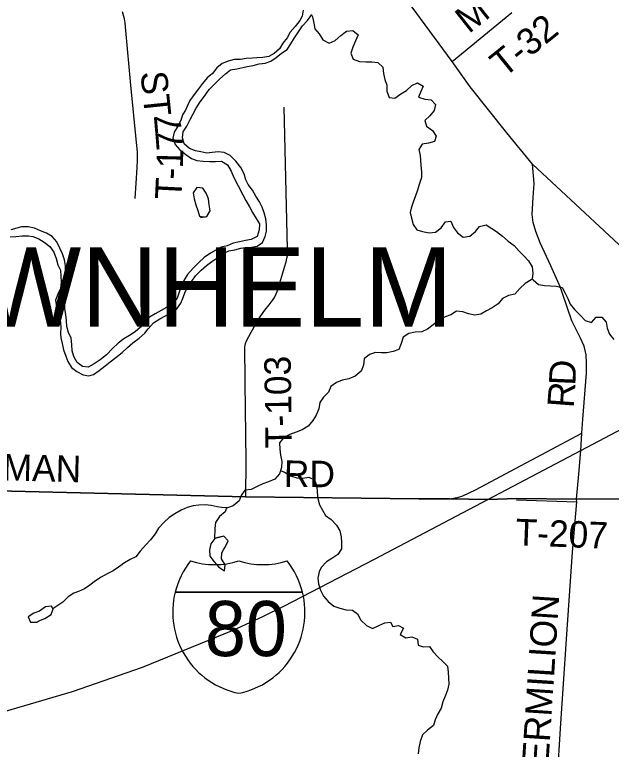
# Model space of a CAD drawing. Extents: x 1857828 to 2277390, y 930619 to 1324581.
# Drawn here: x 2017313 to 2024079, y 1218721 to 1227047 of the extents above; entities that cross this region are included whole.
import ezdxf

# ---------------------------------------------------------------- set-up
doc = ezdxf.new("R2010")
doc.units = 0
for name, color, linetype in [('GM_X_County_Road', 7, 'Continuous'), ('GM_X_County_Road_Text', 7, 'Continuous'), ('GM_X_Interstate_Location', 7, 'Continuous'), ('GM_X_Interstate_Route', 7, 'Continuous'), ('GM_X_Interstate_Shield', 7, 'Continuous'), ('GM_X_Major_River', 7, 'Continuous'), ('GM_X_Minor_Lake', 7, 'Continuous'), ('GM_X_Minor_River', 7, 'Continuous'), ('GM_X_Township', 7, 'Continuous'), ('GM_X_Township_Road', 7, 'Continuous'), ('GM_X_Township_Road_Text', 7, 'Continuous'), ('GM_X_Township_Text', 7, 'Continuous')]:
    doc.layers.add(name, color=color, linetype=linetype)

msp = doc.modelspace()

# ---------------------------------------------------------------- linework, layer by layer
at = {"layer": 'GM_X_County_Road'}
for points in [[(2023524, 1223889.1), (2023501.2, 1223954.9), (2023392.7, 1224201.3), (2023273.2, 1224460.6), (2023223.6, 1224589.3), (2023194.1, 1224690.4), (2023183.1, 1224782.4), (2023192.3, 1224973.6), (2023205.2, 1225135.4), (2023185.7, 1225354.8), (2022892.6, 1225709.1), (2022478.9, 1226229.4), (2022273.7, 1226516.8), (2021768.4, 1227206.3)], [(2023758.2, 1222462), (2023799.1, 1222984.1), (2023799.1, 1223101.8), (2023793.6, 1223193.7), (2023769.7, 1223291.2), (2023729.2, 1223379.4), (2023631.7, 1223578), (2023524, 1223889.1)], [(2023709.6, 1221840.2), (2023734.8, 1222108.8), (2023745.8, 1222303.8), (2023758.2, 1222462)], [(2022306.8, 1221569.9), (2022322.5, 1221573), (2022394.4, 1221594), (2022537.5, 1221662.4), (2023745.8, 1222303.8)], [(2023440.5, 1217534.1), (2023436.9, 1217765.8), (2023455.2, 1218056.3), (2023470, 1218403.9), (2023503, 1218957.3), (2023572.9, 1219968.6), (2023641, 1220954.2), (2023686.9, 1221526), (2023682.9, 1221555.4), (2023709.6, 1221840.2)], [(2015030.8, 1221599.6), (2015061.7, 1221639.5), (2015109.2, 1221673.3), (2015190.9, 1221697.6), (2015867.4, 1221681.1), (2019935.7, 1221581.7), (2021894.8, 1221560.6), (2022115.5, 1221560.6), (2022248.1, 1221558.4), (2022306.8, 1221569.9)]]:
    msp.add_lwpolyline(points, dxfattribs=at)
at = {"layer": 'GM_X_Interstate_Route'}
msp.add_lwpolyline([(2011181, 1217986.5), (2011653.1, 1218164.7), (2012525.4, 1218383.3), (2013202, 1218499.1), (2014599.8, 1218663.4), (2015089, 1218725), (2015558.7, 1218795.2), (2015871.8, 1218846.8), (2016489.7, 1218975.6), (2017209.2, 1219152), (2017969.7, 1219375.9), (2018763.4, 1219652.2), (2019792.4, 1220072.2), (2020127.3, 1220226), (2020366, 1220343.2), (2021393.6, 1220875.2), (2022677.5, 1221551.7), (2023734.8, 1222108.8), (2024759, 1222649.6)], dxfattribs=at)
at = {"layer": 'GM_X_Interstate_Shield'}
for p, q in [((2019134.2, 1220504.2), (2020577, 1220504.2)), ((2020577, 1220504.2), (2019134.2, 1220504.2)), ((2020577, 1220504.2), (2019134.2, 1220504.2))]:
    msp.add_line(p, q, dxfattribs=at)
for centre, start, end in [((2020043.1, 1220274.3), 141.66896, 165.80665), ((2019581.7, 1221752.3), 253.00908, 286.99093), ((2020129.6, 1221752.3), 253.00908, 286.99093), ((2019668.1, 1220274.3), 14.19335, 38.33104), ((2020043.1, 1220274.3), 165.80665, 258.46304), ((2019668.1, 1220274.3), 281.53696, 14.19335)]:
    msp.add_arc(centre, 937.5, start, end, dxfattribs=at)
at = {"layer": 'GM_X_Major_River'}
for points in [[(2020586.2, 1227097.1), (2020572.9, 1227030.8), (2020545.4, 1226980.3), (2020495.9, 1226913.5), (2020438.4, 1226848.6), (2020405, 1226784), (2020353.5, 1226723.3), (2020316, 1226658.6), (2020256.4, 1226605.8), (2020194.5, 1226572.9), (2020126.3, 1226562.1), (2020060.1, 1226557.3), (2020009.9, 1226554.8), (2019937.6, 1226551.9), (2019873.5, 1226541.1), (2019801.2, 1226540.3), (2019735.1, 1226521.5), (2019667.2, 1226492.6), (2019605.4, 1226443.8), (2019558, 1226381), (2019496.3, 1226330.1), (2019444.7, 1226269.3), (2019397.2, 1226208.6), (2019349.8, 1226141.8), (2019298.3, 1226075), (2019276.8, 1226024.6), (2019249.3, 1225964.1), (2019217.8, 1225913.6), (2019198.5, 1225847.1), (2019165, 1225782.6), (2019121.6, 1225717.8), (2019108.3, 1225647.5)], [(2019216.7, 1225652.7), (2019224, 1225721), (2019265.4, 1225783.7), (2019300.9, 1225850.3), (2019332.2, 1225916.9), (2019371.6, 1225989.6), (2019415, 1226058.3), (2019466.5, 1226125.1), (2019519.9, 1226198), (2019575.4, 1226256.8), (2019641, 1226321.8), (2019704.6, 1226376.7), (2019760.3, 1226421.5), (2019832.5, 1226434.3), (2019900.6, 1226449.2), (2019950.7, 1226461.8), (2020016.9, 1226472.6), (2020085, 1226489.4), (2020153.2, 1226496.2), (2020217.2, 1226521), (2020278.9, 1226563.9), (2020338.6, 1226612.7), (2020402.4, 1226653.6), (2020445.9, 1226718.3), (2020487.3, 1226787), (2020530.7, 1226853.7), (2020578.2, 1226920.5), (2020635.7, 1226983.3), (2020683.2, 1227050.1)], [(2017261.1, 1224528.6), (2017327.4, 1224533.4), (2017399.6, 1224542.2), (2017469.9, 1224541), (2017520.2, 1224531.6), (2017586.7, 1224508.3), (2017649.4, 1224470.9), (2017712.3, 1224419.4), (2017757.2, 1224355.8), (2017782.1, 1224285.8), (2017803, 1224213.8), (2017833.8, 1224150), (2017836.6, 1224083.8), (2017839.4, 1224015.6), (2017832.1, 1223945.3), (2017802.7, 1223880.7), (2017775.4, 1223812.2), (2017782, 1223762.1), (2017800.8, 1223698.1), (2017821.7, 1223626.1), (2017834.5, 1223554.1), (2017835.1, 1223503.9), (2017833.9, 1223435.7), (2017836.5, 1223383.5), (2017851.3, 1223319.5), (2017868.1, 1223249.4), (2017893, 1223177.5), (2017917.8, 1223115.6), (2017956.8, 1223047.8), (2018017.5, 1223004.4), (2018088.2, 1222967.1), (2018154.6, 1222955.8), (2018206.7, 1222968.4), (2018270.5, 1223013.3), (2018338.1, 1223068.3), (2018397.9, 1223113.1), (2018459.6, 1223162), (2018531.3, 1223217), (2018590.9, 1223273.8), (2018654.5, 1223328.8), (2018724.2, 1223381.7), (2018789.9, 1223436.6), (2018825.5, 1223487.2), (2018889, 1223556.2), (2018958.8, 1223599.1), (2019022.7, 1223634), (2019084.5, 1223668.8), (2019152.3, 1223713.7), (2019195.8, 1223776.4), (2019223.2, 1223840.9), (2019246.5, 1223907.4), (2019276, 1223961.9), (2019321.5, 1224026.7), (2019363, 1224089.4), (2019426.5, 1224150.3), (2019490.2, 1224205.2), (2019549.9, 1224250), (2019615.7, 1224296.9), (2019679.5, 1224341.8), (2019741.4, 1224370.6), (2019809.5, 1224383.4), (2019877.6, 1224402.3), (2019927.8, 1224406.9), (2019998, 1224413.7), (2020064.2, 1224422.5), (2020121.9, 1224465.3), (2020155.3, 1224533.9), (2020168.7, 1224594.2), (2020169.9, 1224664.5), (2020161.1, 1224734.6), (2020144.2, 1224802.6), (2020119.4, 1224866.6), (2020088.6, 1224926.4), (2020049.7, 1224990.2), (2020008.8, 1225057.9), (2019959.8, 1225123.6), (2019933.1, 1225177.4), (2019914.3, 1225245.4), (2019877.3, 1225315.2), (2019822.3, 1225386.8), (2019755.3, 1225452.3), (2019688.6, 1225485.6), (2019622.2, 1225492.9), (2019552, 1225484), (2019491.8, 1225479.3), (2019423.4, 1225492.6), (2019363, 1225505.9), (2019294.4, 1225529.2), (2019235.6, 1225584.7), (2019216.7, 1225652.7)], [(2019108.3, 1225647.5), (2019133.2, 1225575.5), (2019186.2, 1225513.9), (2019253, 1225462.5), (2019317.8, 1225417.1), (2019380.3, 1225393.8), (2019452.7, 1225386.6), (2019521, 1225383.4), (2019591.3, 1225384.2), (2019659.6, 1225387), (2019726.3, 1225345.6), (2019767.3, 1225273.8), (2019796.2, 1225210), (2019900.9, 1225006.5), (2019933.8, 1224940.7), (2019974.7, 1224870.9), (2020011.6, 1224805.1), (2020050.6, 1224737.4), (2020089.4, 1224675.6), (2020086.2, 1224607.3), (2020064.9, 1224534.9), (2019995, 1224499.9), (2019930.9, 1224489.2), (2019862.8, 1224472.3), (2019790.6, 1224457.5), (2019722.7, 1224428.6), (2019656.5, 1224413.8), (2019594.7, 1224378.9), (2019532.8, 1224346.1), (2019463, 1224297.2), (2019403.5, 1224238.3), (2019337.9, 1224175.3), (2019274.4, 1224102.4), (2019231, 1224035.7), (2019201.7, 1223967.1), (2019178.3, 1223902.6), (2019155, 1223834.1), (2019105.4, 1223773.4), (2019033.6, 1223728.4), (2018973.8, 1223693.6), (2018907.9, 1223656.7), (2018842.1, 1223617.8), (2018778.4, 1223566.9), (2018740.9, 1223506.3), (2018681.3, 1223451.4), (2018615.4, 1223412.6), (2018551.6, 1223373.7), (2018485.9, 1223322.8), (2018422.3, 1223263.9), (2018352.8, 1223192.8), (2018283.2, 1223135.8), (2018215.4, 1223090.9), (2018147.5, 1223054), (2018083.1, 1223061.3), (2018020.4, 1223104.7), (2017983.5, 1223172.5), (2017966.7, 1223236.5), (2017961.8, 1223308.7), (2017953, 1223380.8), (2017922.1, 1223446.7), (2017905.3, 1223514.7), (2017900.5, 1223582.9), (2017893.7, 1223647), (2017882.9, 1223717.1), (2017882.1, 1223785.3), (2017885.4, 1223849.6), (2017888.7, 1223917.8), (2017893.9, 1223984.1), (2017891.1, 1224056.3), (2017889.5, 1224200.8), (2017878.7, 1224268.9), (2017853.8, 1224338.8), (2017826.9, 1224402.7), (2017790, 1224472.5), (2017737.1, 1224534.1), (2017672.4, 1224571.5), (2017605.8, 1224596.8), (2017537.2, 1224626.1), (2017464.7, 1224641.3), (2017392.4, 1224642.5), (2017336.3, 1224627.8), (2017270.3, 1224609)]]:
    msp.add_lwpolyline(points, dxfattribs=at)
at = {"layer": 'GM_X_Minor_Lake'}
for points in [[(2019447.1, 1225082.9), (2019380.9, 1225087.7), (2019336, 1225028), (2019349.3, 1224959.6), (2019368.5, 1224891.2), (2019391.9, 1224826.7), (2019409.2, 1224762.3), (2019457.3, 1224755.7)], [(2019447.1, 1225082.9), (2019380.9, 1225087.7), (2019336, 1225028), (2019349.3, 1224959.6), (2019368.5, 1224891.2), (2019391.9, 1224826.7), (2019409.2, 1224762.3), (2019473.3, 1224753.5)], [(2019421.1, 1224750.1), (2019493.5, 1224761.3), (2019528.4, 1224823.1), (2019519.2, 1224891.4), (2019510, 1224961.8), (2019484.6, 1225026.3), (2019447.1, 1225082.9)], [(2019457.3, 1224755.7), (2019493.5, 1224761.3), (2019528.4, 1224823.1), (2019519.2, 1224891.4), (2019510, 1224961.8), (2019484.6, 1225026.3), (2019447.1, 1225082.9)], [(2019615.5, 1221120.9), (2019581.5, 1221110.2), (2019538, 1221049.5), (2019522.7, 1220981.1), (2019525.5, 1220910.9), (2019576.4, 1220845.3), (2019627.3, 1220785.7), (2019694.1, 1220744.3), (2019699.3, 1220810.6), (2019660.4, 1220880.4), (2019661.6, 1220948.6), (2019686.1, 1220991)], [(2019612.5, 1221120), (2019581.5, 1221110.2), (2019538, 1221049.5), (2019522.7, 1220981.1), (2019525.5, 1220910.9), (2019576.4, 1220845.3), (2019627.3, 1220785.7), (2019694.1, 1220744.3), (2019699.3, 1220810.6), (2019660.4, 1220880.4), (2019661.6, 1220948.6), (2019686.1, 1220991)], [(2019686.1, 1220991), (2019699.1, 1221013.3), (2019734.4, 1221085.9), (2019683.6, 1221135.5), (2019612.5, 1221120)], [(2019686.1, 1220991), (2019699.1, 1221013.3), (2019734.4, 1221085.9), (2019683.6, 1221135.5), (2019615.5, 1221120.7)], [(2017748.5, 1220312.8), (2017732.3, 1220344.5), (2017664.1, 1220337.7), (2017596.4, 1220286.7), (2017532.3, 1220265.9), (2017466.5, 1220223.1), (2017491.3, 1220161.1), (2017563.6, 1220164)], [(2017748.6, 1220312.8), (2017732.3, 1220344.5), (2017664.1, 1220337.7), (2017596.4, 1220286.7), (2017532.3, 1220265.9), (2017466.5, 1220223.1), (2017491.3, 1220161.1), (2017563.6, 1220164)], [(2017563.6, 1220164), (2017587.6, 1220176.3), (2017655.5, 1220205.2), (2017725.4, 1220248.1), (2017748.5, 1220312.8)], [(2017563.6, 1220164), (2017587.6, 1220176.3), (2017655.5, 1220205.2), (2017725.4, 1220248.1), (2017748.5, 1220312.8)]]:
    msp.add_lwpolyline(points, dxfattribs=at)
at = {"layer": 'GM_X_Minor_River'}
for points in [[(2020679.9, 1227045.5), (2020689.5, 1227024.1), (2020704.4, 1226952), (2020717.2, 1226886), (2020766, 1226832.3), (2020806.9, 1226762.6), (2020879.7, 1226723.3), (2020947.6, 1226756.2), (2021013.3, 1226811.1), (2021076.9, 1226862), (2021149.2, 1226868.9), (2021208, 1226819.4), (2021178.6, 1226750.8), (2021147.3, 1226678.2), (2021126, 1226611.8), (2021152.9, 1226543.9), (2021225.5, 1226516.6), (2021297.8, 1226513.4), (2021364.1, 1226514.2), (2021432.5, 1226504.9), (2021487.3, 1226451.4), (2021494.2, 1226379.2), (2021511, 1226311.2), (2021533.8, 1226249.3), (2021534.6, 1226181.1), (2021559.5, 1226109.1), (2021625.8, 1226101.8), (2021691.6, 1226150.8), (2021755.4, 1226189.6), (2021817, 1226244.5), (2021883, 1226275.4), (2021945.7, 1226236), (2021918.2, 1226177.4), (2021892.9, 1226110.9), (2021965.4, 1226091.7), (2022037.8, 1226082.5), (2022086.6, 1226028.9), (2022069.3, 1225962.5), (2022019.8, 1225899.7), (2021964.1, 1225848.9), (2021984.9, 1225782.9), (2022051.8, 1225733.6), (2022092.6, 1225671.8), (2022075.3, 1225609.4), (2022007.2, 1225590.6), (2021935, 1225581.7), (2021895.5, 1225521.1), (2021910.4, 1225453), (2021916.9, 1225402.9), (2021917.7, 1225338.7), (2021926.5, 1225266.6), (2021925.3, 1225200.4), (2021900, 1225123.8), (2021880.7, 1225059.4), (2021857.3, 1224992.9), (2021832, 1224922.4), (2021808.6, 1224855.9), (2021799.2, 1224805.6), (2021814, 1224741.6), (2021832.8, 1224669.6), (2021873.7, 1224607.9), (2021938.2, 1224588.6), (2022012.7, 1224573.3), (2022084.9, 1224584.2), (2022148.6, 1224631.1), (2022198.1, 1224697.9), (2022260.2, 1224708.6), (2022289.1, 1224636.7), (2022334, 1224575.1), (2022400.8, 1224527.7), (2022473, 1224538.5), (2022538.7, 1224591.4), (2022586.3, 1224646.2), (2022658.4, 1224667.1), (2022725.1, 1224625.7), (2022775.7, 1224590.2), (2022844.6, 1224536.8), (2022909.5, 1224481.3), (2022976.4, 1224429.9), (2023035.3, 1224368.4), (2023088.2, 1224312.9), (2023139, 1224257.3), (2023180, 1224189.5), (2023188.8, 1224119.4), (2023183.5, 1224053.1)], [(2023183.5, 1224053.1), (2023169.6, 1224040.9), (2023103.8, 1224000), (2023040.1, 1223945.1), (2022984.6, 1223880.3), (2022912.5, 1223865.4), (2022846.6, 1223830.5), (2022795.1, 1223769.7), (2022729.3, 1223726.8), (2022665.4, 1223690), (2022599.5, 1223653.1), (2022531.4, 1223640.3), (2022460.9, 1223657.5), (2022396.4, 1223678.9), (2022324, 1223686.1), (2022258.2, 1223647.2), (2022194.2, 1223622.4), (2022126.3, 1223585.5), (2022060.7, 1223530.5), (2021994.9, 1223483.6), (2021928.9, 1223454.8), (2021856.7, 1223447.9), (2021784.6, 1223435.1), (2021718.8, 1223392.2), (2021697.5, 1223321.7), (2021668.1, 1223253.1), (2021606.1, 1223230.3), (2021534, 1223215.5), (2021471.7, 1223214.8), (2021403.4, 1223220), (2021337.3, 1223197.1), (2021277.7, 1223148.3), (2021268.4, 1223076), (2021241.1, 1223007.4), (2021173.4, 1222950.5), (2021101.5, 1222921.6), (2021027.3, 1222904.6), (2020961.4, 1222877.8), (2020899.6, 1222832.9), (2020872.2, 1222768.4), (2020816.6, 1222711.6), (2020775.1, 1222652.9), (2020761.9, 1222580.6), (2020732.5, 1222510), (2020695.1, 1222447.3), (2020641.6, 1222382.5), (2020573.8, 1222341.6), (2020503.8, 1222314.7), (2020431.8, 1222289.8), (2020363.8, 1222256.9), (2020316.3, 1222194.2), (2020319.2, 1222122), (2020326, 1222055.8), (2020342.8, 1221983.8), (2020337.6, 1221913.5), (2020316.3, 1221845.1), (2020262.7, 1221784.2), (2020192.8, 1221753.3), (2020128.8, 1221728.5), (2020062.9, 1221699.7), (2019997, 1221664.8), (2019924.7, 1221657.9), (2019883.2, 1221599.3), (2019857.8, 1221536.8), (2019792.2, 1221481.8), (2019728.2, 1221459), (2019659.8, 1221462.3), (2019609.6, 1221467.7), (2019541.1, 1221483), (2019474.7, 1221492.2), (2019402.5, 1221487.4), (2019336.3, 1221480.6), (2019270.2, 1221463.8), (2019200.2, 1221432.9), (2019128.4, 1221389.9), (2019064.6, 1221349.1), (2019005, 1221290.2), (2018945.5, 1221227.3), (2018906, 1221162.6), (2018854.6, 1221093.8), (2018797, 1221035), (2018737.5, 1220968.1), (2018686, 1220903.3), (2018622.1, 1220872.4), (2018560.3, 1220833.6), (2018490.5, 1220786.6), (2018428.7, 1220743.8), (2018362.8, 1220708.9), (2018293, 1220672), (2018229.2, 1220629.1), (2018167.5, 1220580.3), (2018103.7, 1220539.4), (2018035.7, 1220510.5), (2017983.7, 1220489.9), (2017919.9, 1220449), (2017860.3, 1220388.1), (2017747.6, 1220314.6)], [(2023183.5, 1224053.1), (2023194.6, 1224041.2), (2023254.3, 1223988.3), (2023322.4, 1223977.5), (2023390.7, 1223972.7), (2023454.9, 1223971.9), (2023523, 1223955), (2023556.4, 1223890.4), (2023587.8, 1223829.9), (2023613.2, 1223767.4), (2023662.6, 1223704.6), (2023726.2, 1223643.6), (2023783.7, 1223580.7), (2023853.7, 1223557.8), (2023908.7, 1223619.4), (2023972.9, 1223618.6), (2024020.5, 1223561.9), (2024033.7, 1223493.5), (2024057, 1223427), (2024108.5, 1223366.2)], [(2020327.5, 1221881.1), (2020382.4, 1221857.8), (2020443.1, 1221820.4), (2020511.6, 1221799.1), (2020582, 1221793.9), (2020650.1, 1221804.8), (2020714.8, 1221775.4), (2020739.7, 1221703.5), (2020744.5, 1221635.3), (2020751.3, 1221563.1), (2020768.2, 1221493.1), (2020803, 1221431.3), (2020837.8, 1221371.5), (2020900.6, 1221324.1), (2020961.6, 1221262.6), (2021002.5, 1221198.8), (2021017.3, 1221130.8), (2021020.1, 1221064.6), (2021018.9, 1220992.4), (2020979.4, 1220927.7), (2020911.6, 1220882.8), (2020847.8, 1220847.9), (2020790.3, 1220783.1), (2020766.7, 1220732.6), (2020751.5, 1220660.2), (2020760.2, 1220596.1), (2020781.1, 1220524.1), (2020816, 1220456.3), (2020869, 1220394.7), (2020933.8, 1220345.3), (2021002.3, 1220322), (2021070.9, 1220302.7), (2021143.2, 1220297.6), (2021201.9, 1220258.1), (2021238.9, 1220186.3), (2021301.9, 1220122.8), (2021370.5, 1220089.5), (2021442.4, 1220124.4), (2021510.4, 1220153.3), (2021576.5, 1220164.1), (2021603.2, 1220112.2), (2021667.4, 1220125), (2021721.9, 1220095.5), (2021686.6, 1220022.9), (2021749.3, 1219985.5), (2021817.5, 1219996.3), (2021882, 1219971), (2021888.8, 1219902.8), (2021947.3, 1219883.4), (2022017.5, 1219888.3), (2022060.4, 1219824.6), (2022111.3, 1219769), (2022168.1, 1219715.4), (2022220.9, 1219661.9), (2022229.7, 1219595.8), (2022234.5, 1219527.6), (2022235.3, 1219459.4), (2022220, 1219393), (2022196.6, 1219324.5), (2022169.3, 1219258), (2022150, 1219187.5), (2022110.5, 1219124.9), (2022081.2, 1219056.3), (2022061.8, 1218991.9), (2021994.1, 1218936.9), (2021936.5, 1218884.1), (2021911.2, 1218809.6), (2021898, 1218739.2), (2021888.7, 1218670.9)], [(2019715.4, 1221459.6), (2019698.6, 1221412.6), (2019634.9, 1221359.6), (2019591.5, 1221290.9), (2019582.2, 1221222.6), (2019581.2, 1221110.4)]]:
    msp.add_lwpolyline(points, dxfattribs=at)
at = {"layer": 'GM_X_Township'}
for points in [[(2025786.1, 1221567.7), (2023682.8, 1221555.4), (2023008.4, 1221564.6), (2022677.5, 1221551.6), (2022248.1, 1221558.5), (2022115.5, 1221560.6), (2021894.9, 1221560.6), (2019935.7, 1221581.7), (2015867.4, 1221681.1)], [(2015867.4, 1221681.1), (2019935.7, 1221581.7), (2021894.9, 1221560.6), (2022115.5, 1221560.6), (2022248.1, 1221558.5), (2022677.5, 1221551.6), (2023008.4, 1221564.6), (2023682.8, 1221555.4), (2025786.1, 1221567.7)]]:
    msp.add_lwpolyline(points, dxfattribs=at)
at = {"layer": 'GM_X_Township_Road'}
for points in [[(2018678.7, 1224964.7), (2018702.4, 1225311.7), (2018706.3, 1225403.9), (2018706.2, 1225492.1), (2018696.1, 1225598.4), (2018629.2, 1226248), (2018572.3, 1226867.6), (2018566.2, 1226953.8), (2018558.1, 1226999.9), (2018544, 1227052), (2018534.7, 1227081.2)], [(2022273.7, 1226516.8), (2022952.8, 1227070.8)], [(2020320.5, 1224007.1), (2020353.8, 1224121), (2020373.8, 1224185.2), (2020391.8, 1224245.4), (2020399.7, 1224289.6), (2020405.7, 1224313.6), (2020407.6, 1224391.8), (2020368.1, 1226001.1)], [(2025774.1, 1221636.4), (2025770.1, 1221659.5), (2025690.3, 1222126.3), (2025589.3, 1222675.1), (2025559, 1222850.1), (2025532, 1222944.4), (2025502.4, 1223041.1), (2025478.2, 1223119.4), (2025447.9, 1223186.8), (2025404.1, 1223264.2), (2025350.3, 1223345), (2025286.3, 1223439.3), (2025208.9, 1223533.5), (2025047.3, 1223671.5), (2024542.3, 1224092.3), (2023185.7, 1225354.8)], [(2019927.4, 1222901.6), (2019926, 1223011.5), (2019921.8, 1223173.9), (2019921.7, 1223242.1), (2019923.7, 1223282.2), (2019931.7, 1223322.3), (2019943.7, 1223352.4), (2019995.7, 1223450.7), (2020079.8, 1223595.3), (2020149.8, 1223697.6), (2020199.9, 1223757.9), (2020243.9, 1223818.1), (2020259.9, 1223842.2), (2020277.9, 1223884.3), (2020299.9, 1223936.5), (2020307.2, 1223961.4), (2020320.5, 1224007.1)], [(2019935.7, 1221581.7), (2019939.2, 1221986.8), (2019927.8, 1222876.9), (2019927.4, 1222901.6)], [(2023004.7, 1221549.9), (2023686.9, 1221526)]]:
    msp.add_lwpolyline(points, dxfattribs=at)

# ---------------------------------------------------------------- texts
at = {"layer": 'GM_X_County_Road_Text'}
for s, rotation, p in [('D', 87.47437, (2023670.7, 1222840.6)), ('R', 85.76922, (2023652, 1222585.3)), ('PORTMAN', 358.59223, (2016059.3, 1221796.7)), ('RD', 359.50636, (2020365, 1221695.5)), ('VERMILION', 86.33471, (2023347.9, 1218265.4))]:
    msp.add_text(s, height=300, rotation=rotation, dxfattribs=at).set_placement(p)
at = {"layer": 'GM_X_Interstate_Location'}
for s in ['-', '.', ',']:
    msp.add_text(s, height=1, dxfattribs=at).set_placement((2019855.5, 1220105.2))
msp.add_text('80', height=1, rotation=0.00001, dxfattribs=at).set_placement((2019651.2, 1219898.2))
at = {"layer": 'GM_X_Interstate_Shield'}
msp.add_text('80', height=625, dxfattribs=at).set_placement((2019470.4, 1219777.6))
at = {"layer": 'GM_X_Township_Road_Text'}
for s, rotation, p in [('M', 38.30553, (2022462.7, 1226825.5)), ('T-32', 38.82449, (2022860.9, 1226325.2)), ('ST', 275.88724, (2018739, 1226394.4)), ('7', 94.92962, (2019209, 1225708.2)), ('7', 94.67177, (2019224.2, 1225522.6)), ('1', 88.66055, (2019220.9, 1225303.5)), ('-', 87.21449, (2019214.6, 1225172.2)), ('T', 87.09307, (2019203.2, 1224947.4)), ('T-103', 90.83678, (2020457.8, 1222135.3)), ('T-207', 357.75333, (2022988, 1221035.3))]:
    msp.add_text(s, height=300, rotation=rotation, dxfattribs=at).set_placement(p)
at = {"layer": 'GM_X_Township_Text'}
msp.add_text('BROWNHELM', height=900, rotation=0.00001, dxfattribs=at).set_placement((2014324.1, 1223510.5))

doc.saveas('drawing.dxf')
